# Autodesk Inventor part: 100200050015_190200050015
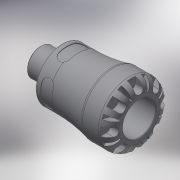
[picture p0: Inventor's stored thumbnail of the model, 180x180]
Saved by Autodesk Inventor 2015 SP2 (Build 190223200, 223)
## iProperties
Created: 2016-12
Part Number: 100200050015_190200050015
Material: Generic
Description: PLASSON MALE ADAPTOR 50X1.1/2" SERIES 1
Document SubType Name: Modeling
Designer: KIM
Mass: 447.839 g
Surface Area: 722.341 cm^2
Volume: 447.839 cm^3
Density: 1 g/cm^3
Appearance: Default
Author: KIM
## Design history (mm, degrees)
derived "1002.ipt"
feature "Solid1::1002.ipt"
tag "TaggingFeature1"
body "Solid1"
other parameters: "d0" = 114, "d1" = 34.02, "d3" = 62.5, "d4" = 85, "d6" = 81, "d8" = 72.25, "d13" = 9, "d14" = 9, "d15" = 0, "d17" = 360 deg, "d19" = 8 deg, "d20" = 1, "d21" = 1, "d22" = 8 deg, "d24" = 0, "d26" = 360 deg, "d32" = 0.925, "d33" = 8.5, "d34" = 47.803, "d35" = 6.25, "d38" = 21, "d39" = 1.43409, "d42" = 17.5, "d43" = 11.5, "d45" = 17.64, "d46" = 0, "d59" = 360 deg, "d61" = 14.875, "d62" = 1, "d64" = 0, "d65" = 0.85, "E_" = 85, "H_" = 114, "l_" = 81, "R_" = 47.803, "l_2" = 21, "d9" = 11.25, "d11" = 85, "d12" = 62.5
